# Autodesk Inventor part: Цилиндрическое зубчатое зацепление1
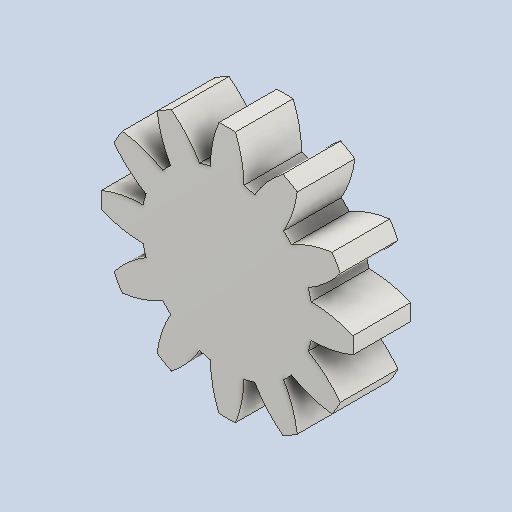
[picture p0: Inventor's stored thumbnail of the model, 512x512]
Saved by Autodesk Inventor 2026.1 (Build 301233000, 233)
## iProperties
Created: 2026-01
Part Number: Цилиндрическое зубчатое зацепление1
Material: Steel
Document SubType Name: Modeling
Designer: Yury Melnikov
Categories: <?xml version="1.0" encoding="UTF-16"?> <MemberInstance><Categories><FamilyTemplate><FamilyTemplateParameter ValueType="xs:double" Id="1" ObjectReferenceKey="da
Density: 1 g/cm^3
Appearance: Steel
CustomPartVersion: 1
Author: Yury Melnikov
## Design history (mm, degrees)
sketch "Sketch1"
  geometry: C1 r 8.75 at (0, 0)
  constraints: 1 centre point
  dimensions: "d0" = 17.5 diameter of C1 (= da_da)
extrude "Extrusion1" new body sketch "Sketch1" distance "d1" = 4 (= da_b); taper "d2" = 0 deg
workplane "Work Plane2"
feature "Средний диаметр" dims "d4" = 10, "d5" = 0
workplane "Work Plane8"
workplane "Work Plane9"
feature "Цилиндрическое зубчатое зацепление" dims "da_b" = 4, "da_d" = 15, "da_aw" = 22.5, "da_da" = 17.5, "da_df" = 11.875, "da_dw" = 15, angle "da_beta" = 0 deg, "da_lefttooth" = 0, "da_righttooth" = 0
body "Solid1"
sketch "Sketch2"
  geometry: C1 r 8.75 at (0, 0) reference; C2 r 7.5 at (0, 0)
  constraints: 1 centre point, 1 coincident
  dimensions: "d3" = 15 diameter of C2 (= da_d)
body "Srf1"
other parameters: "d16" = 22.5 (= da_aw), "d17" = 0, "d34" = 15 deg (computed from da_z), "d39" = 0, "d41" = 0, "d43" = 22.5 (= da_aw), "d46" = 22.5 (= da_aw), "d47" = 0, "d48" = 0
